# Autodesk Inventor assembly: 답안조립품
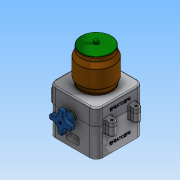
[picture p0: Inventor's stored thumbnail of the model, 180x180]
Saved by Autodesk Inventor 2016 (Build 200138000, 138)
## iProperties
Created: 2018-01
Part Number: 답안조립품
Material: 일반
Document SubType Name: Assembly
Designer: Administrator
Author: Administrator
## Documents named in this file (9)
- C:\Users\Administrator\Desktop\480107V1031\답안조립품.iam
- C:\Users\Administrator\Desktop\480107V1031\본체.ipt
- C:\Users\Administrator\Desktop\480107V1031\핸들축.ipt
- C:\Users\Administrator\Desktop\480107V1031\본체커버.ipt
- C:\Users\Administrator\Desktop\480107V1031\핸들.ipt
- C:\Users\Administrator\Desktop\480107V1031\볼트 M3x12.ipt
- C:\Users\Administrator\Desktop\480107V1031\용기캡.ipt
- C:\Users\Administrator\Desktop\480107V1031\용기.ipt
- C:\Users\Administrator\Desktop\480107V1031\볼트 M4x12.ipt
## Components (2 placed, 2 different names)
1. 핸들축:1
2. 핸들:1
